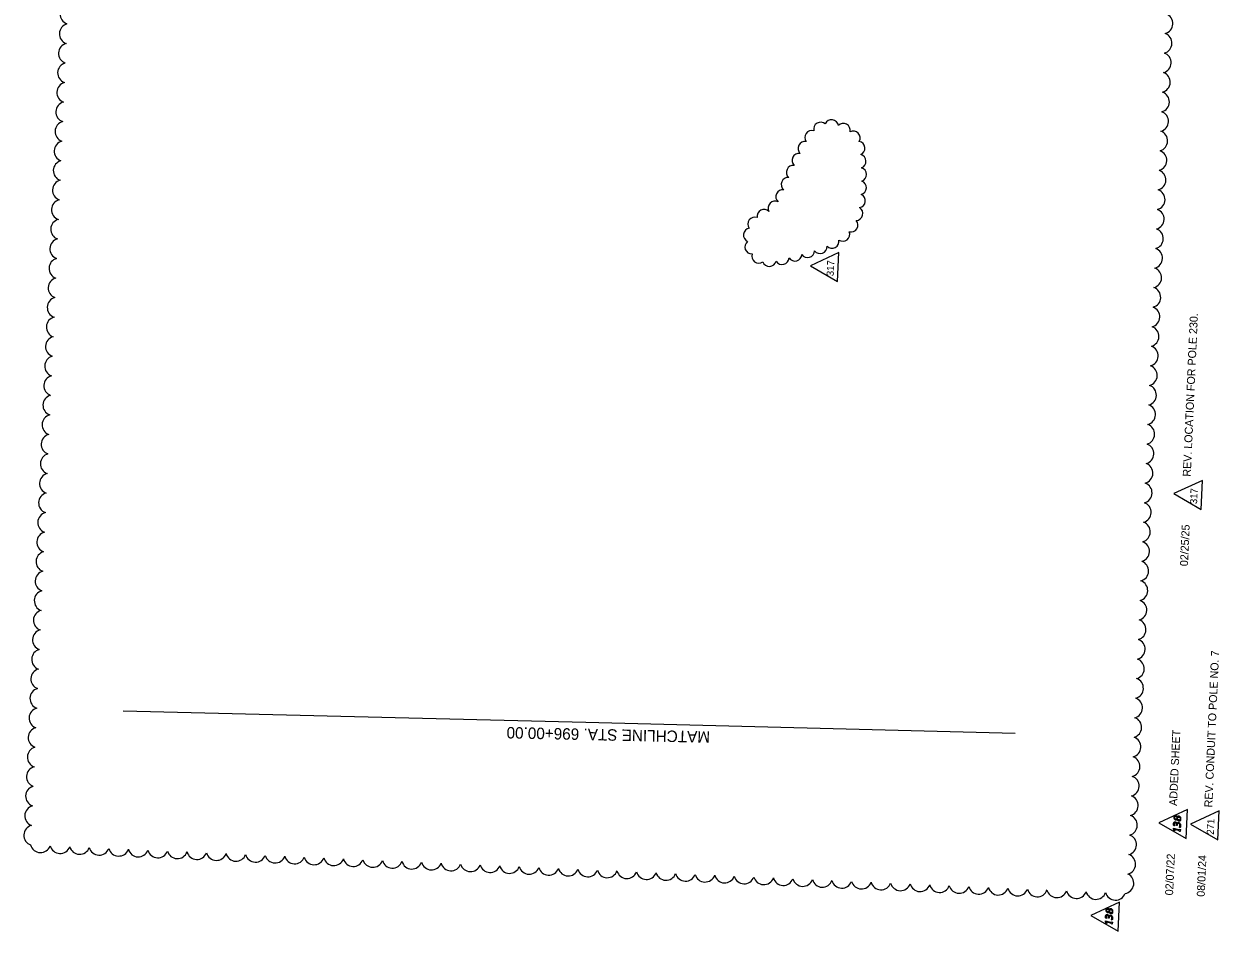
# Model space of a CAD drawing. Extents: x 928596 to 929473, y 645293 to 646588.
# Drawn here: x 928596 to 929432, y 645293 to 645927 of the extents above; entities that cross this region are included whole.
import ezdxf

# ---------------------------------------------------------------- set-up
doc = ezdxf.new("R2010")
doc.units = 0
for name, color, linetype in [('Cloud_dp', 7, 'Continuous'), ('LeaderLine_dp', 7, 'Continuous'), ('PavtAsphalt', 7, 'Continuous'), ('TextBLStation', 7, 'Continuous')]:
    doc.layers.add(name, color=color, linetype=linetype)

msp = doc.modelspace()

# ---------------------------------------------------------------- linework, layer by layer
at = {"layer": 'Cloud_dp'}
for points in [[(929145.88, 645758.1), (929164.93, 645747.11), (929165.83, 645767.37)], [(929400.15, 645598.64), (929419.21, 645587.65), (929420.11, 645607.91)], [(929389.76, 645368.39), (929408.81, 645357.39), (929409.71, 645377.65)], [(929411.88, 645367.41), (929430.93, 645356.41), (929431.83, 645376.67)]]:
    msp.add_lwpolyline(points, close=True, dxfattribs=at)
for points in [[(929400.66, 645366.19), (929400.11, 645366.33)], [(929402.51, 645366.97), (929402.48, 645366.41), (929401.99, 645366.54), (929402.01, 645367.1)], [(929404.16, 645362.38), (929404.18, 645362.81), (929400.45, 645363.78), (929400.8, 645362.74), (929400.18, 645363), (929399.88, 645363.89), (929399.91, 645364.55), (929404.21, 645363.43), (929404.22, 645363.86), (929404.75, 645363.68), (929404.69, 645362.21), (929404.16, 645362.38)], [(929404.59, 645365.02), (929404.02, 645365.18)]]:
    msp.add_lwpolyline(points, dxfattribs=at)
for centre, radius, start, end in [((929160.66, 645855.3), 4.88, 10.34775, 155.34775), ((929146.78, 645847.82), 4.88, 71.57237, 216.57237), ((929153.04, 645853.64), 4.88, 49.19055, 194.19055), ((929168.88, 645852.7), 4.88, 349.57651, 134.57651), ((929175.82, 645847.44), 4.87, 331.1026, 116.1026), ((929142.02, 645840.11), 4.88, 80.0905, 225.0905), ((929179.11, 645840.31), 4.87, 293.42764, 78.42764), ((929137.86, 645831.84), 4.88, 81.54291, 226.54291), ((929179.84, 645831.11), 4.88, 290.65011, 75.65011), ((929133.93, 645823.46), 4.88, 83.18854, 228.18854), ((929180.23, 645821.86), 4.88, 289.24861, 74.24861), ((929130.31, 645814.96), 4.88, 85.63768, 230.63768), ((929180.17, 645812.68), 4.88, 284.95621, 69.95621), ((929126.57, 645806.36), 4.88, 82.32238, 227.32238), ((929121.12, 645798.4), 4.88, 63.88587, 208.88587), ((929179.42, 645803.52), 4.88, 280.64089, 65.64089), ((929106.98, 645787.14), 4.88, 70.43464, 215.43464), ((929113.41, 645792.59), 4.88, 45.1131, 190.1131), ((929177.7, 645794.62), 4.88, 272.5508, 57.5508), ((929103.89, 645779.52), 4.88, 100.46864, 245.46864), ((929174.23, 645786.56), 4.88, 255.8672, 40.8672), ((929160.98, 645775.18), 4.88, 225.07197, 10.07197), ((929168.49, 645780.08), 4.88, 236.10245, 21.10245), ((929104.86, 645771.24), 4.88, 127.87411, 272.87411), ((929143.94, 645768.66), 4.88, 213.21508, 358.21508), ((929152.66, 645771.49), 4.88, 217.76468, 2.76468), ((929109.72, 645764.8), 4.88, 161.1794, 306.1794), ((929117.19, 645762.49), 4.88, 199.49851, 344.49851), ((929126.01, 645763.79), 4.88, 212.2389, 357.2389), ((929134.99, 645766.18), 4.88, 212.67182, 357.67182)]:
    msp.add_arc(centre, radius, start, end, dxfattribs=at)
for points in [[(929400.11, 645366.33), (929400.03, 645366.7), (929400, 645367.04), (929399.96, 645367.37), (929399.97, 645367.66), (929400.01, 645368.4), (929400.35, 645368.74), (929400.62, 645369), (929401.01, 645368.98), (929401.14, 645368.98), (929401.28, 645368.94), (929401.66, 645368.84), (929401.92, 645368.55), (929402.17, 645368.26), (929402.27, 645367.74)], [(929402.45, 645371.06), (929402.31, 645370.61), (929402.01, 645370.46), (929401.82, 645370.35), (929401.57, 645370.36), (929401.45, 645370.37), (929401.32, 645370.4), (929400.76, 645370.54), (929400.45, 645371.03), (929400.14, 645371.52), (929400.18, 645372.22), (929400.21, 645372.94), (929400.55, 645373.26), (929400.82, 645373.5), (929401.2, 645373.48), (929401.33, 645373.47), (929401.48, 645373.44), (929401.87, 645373.33), (929402.14, 645373.04), (929402.41, 645372.74), (929402.5, 645372.23), (929402.64, 645372.72), (929402.98, 645372.9), (929403.19, 645373.02), (929403.47, 645373.01), (929403.61, 645373), (929403.76, 645372.96), (929404.44, 645372.78), (929404.78, 645372.27), (929405.12, 645371.76), (929405.09, 645370.97), (929405.05, 645370.18), (929404.67, 645369.85), (929404.39, 645369.62), (929403.97, 645369.64), (929403.79, 645369.64), (929403.59, 645369.69), (929403.14, 645369.81), (929402.84, 645370.15), (929402.55, 645370.49), (929402.45, 645371.06)], [(929402.01, 645367.1), (929402.03, 645367.58), (929401.85, 645367.9), (929401.66, 645368.22), (929401.29, 645368.31), (929401.19, 645368.34), (929401.1, 645368.34), (929400.87, 645368.35), (929400.72, 645368.2), (929400.5, 645367.98), (929400.48, 645367.49), (929400.47, 645367.23), (929400.51, 645366.9), (929400.56, 645366.58), (929400.66, 645366.19)], [(929401.43, 645371), (929401.54, 645370.97), (929401.64, 645370.96), (929401.87, 645370.95), (929402.02, 645371.08), (929402.24, 645371.26), (929402.26, 645371.68), (929402.28, 645372.11), (929402.07, 645372.41), (929401.86, 645372.72), (929401.48, 645372.81), (929401.37, 645372.84), (929401.28, 645372.85), (929401.05, 645372.86), (929400.9, 645372.73), (929400.67, 645372.54), (929400.66, 645372.12), (929400.64, 645371.69), (929400.84, 645371.39), (929401.05, 645371.1), (929401.43, 645371)], [(929402.27, 645367.74), (929402.41, 645368.23), (929402.73, 645368.41), (929402.95, 645368.53), (929403.22, 645368.52), (929403.36, 645368.52), (929403.51, 645368.48), (929404.21, 645368.3), (929404.56, 645367.72), (929404.92, 645367.14), (929404.88, 645366.25), (929404.87, 645365.94), (929404.79, 645365.64), (929404.72, 645365.33), (929404.59, 645365.02)], [(929404.02, 645365.18), (929404.16, 645365.38), (929404.26, 645365.68), (929404.35, 645365.98), (929404.37, 645366.33), (929404.39, 645366.95), (929404.16, 645367.35), (929403.93, 645367.74), (929403.46, 645367.86), (929403.34, 645367.89), (929403.24, 645367.9), (929402.96, 645367.91), (929402.79, 645367.74), (929402.53, 645367.5), (929402.51, 645366.97)], [(929402.73, 645371.59), (929402.71, 645371.11), (929402.95, 645370.77), (929403.2, 645370.43), (929403.64, 645370.32), (929403.77, 645370.28), (929403.89, 645370.28), (929404.15, 645370.26), (929404.33, 645370.4), (929404.59, 645370.61), (929404.61, 645371.07), (929404.63, 645371.55), (929404.39, 645371.89), (929404.14, 645372.23), (929403.7, 645372.34), (929403.57, 645372.38), (929403.45, 645372.38), (929403.19, 645372.39), (929403.01, 645372.26), (929402.75, 645372.06), (929402.73, 645371.59)]]:
    msp.add_open_spline(points, degree=3, dxfattribs=at)
at = {"layer": 'LeaderLine_dp'}
msp.add_lwpolyline([(929342.17, 645303.59), (929361.23, 645292.6), (929362.13, 645312.86)], close=True, dxfattribs=at)
for points in [[(929356.58, 645297.58), (929356.59, 645298.02), (929352.87, 645298.98), (929353.21, 645297.95), (929352.6, 645298.21), (929352.3, 645299.1), (929352.33, 645299.75), (929356.62, 645298.64), (929356.64, 645299.06), (929357.17, 645298.88), (929357.1, 645297.42), (929356.58, 645297.58)], [(929353.08, 645301.4), (929352.53, 645301.54)], [(929354.93, 645302.17), (929354.9, 645301.61), (929354.4, 645301.75), (929354.43, 645302.3)], [(929357, 645300.23), (929356.43, 645300.38)]]:
    msp.add_lwpolyline(points, dxfattribs=at)
for centre, radius, start, end in [((928628.13, 645933.99), 7.18, 104.96475, 249.96475), ((929392.27, 645927.48), 7.18, 284.96475, 69.96475), ((928627.52, 645920.31), 7.18, 104.96475, 249.96475), ((929391.67, 645913.8), 7.18, 284.96475, 69.96475), ((928626.92, 645906.64), 7.18, 104.96475, 249.96475), ((929391.06, 645900.13), 7.18, 284.96475, 69.96475), ((928626.31, 645892.96), 7.18, 104.96475, 249.96475), ((929390.46, 645886.45), 7.18, 284.96475, 69.96475), ((928625.71, 645879.28), 7.18, 104.96475, 249.96475), ((929389.85, 645872.77), 7.18, 284.96475, 69.96475), ((928625.1, 645865.61), 7.18, 104.96475, 249.96475), ((929389.24, 645859.1), 7.18, 284.96475, 69.96475), ((928624.5, 645851.93), 7.18, 104.96475, 249.96475), ((929388.64, 645845.42), 7.18, 284.96475, 69.96475), ((928623.89, 645838.26), 7.18, 104.96475, 249.96475), ((929388.03, 645831.75), 7.18, 284.96475, 69.96475), ((928623.28, 645824.58), 7.18, 104.96475, 249.96475), ((928622.68, 645810.9), 7.18, 104.96475, 249.96475), ((929387.43, 645818.07), 7.18, 284.96475, 69.96475), ((929386.82, 645804.39), 7.18, 284.96475, 69.96475), ((928622.07, 645797.23), 7.18, 104.96475, 249.96475), ((929386.22, 645790.72), 7.18, 284.96475, 69.96475), ((928621.47, 645783.55), 7.18, 104.96475, 249.96475), ((929385.61, 645777.04), 7.18, 284.96475, 69.96475), ((928620.86, 645769.87), 7.18, 104.96475, 249.96475), ((929385.01, 645763.36), 7.18, 284.96475, 69.96475), ((928620.26, 645756.2), 7.18, 104.96475, 249.96475), ((929384.4, 645749.69), 7.18, 284.96475, 69.96475), ((928619.65, 645742.52), 7.18, 104.96475, 249.96475), ((929383.79, 645736.01), 7.18, 284.96475, 69.96475), ((928619.05, 645728.84), 7.18, 104.96475, 249.96475), ((929383.19, 645722.33), 7.18, 284.96475, 69.96475), ((928618.44, 645715.17), 7.18, 104.96475, 249.96475), ((928617.83, 645701.49), 7.18, 104.96475, 249.96475), ((929382.58, 645708.66), 7.18, 284.96475, 69.96475), ((929381.98, 645694.98), 7.18, 284.96475, 69.96475), ((928617.23, 645687.81), 7.18, 104.96475, 249.96475), ((929381.37, 645681.31), 7.18, 284.96475, 69.96475), ((928616.62, 645674.14), 7.18, 104.96475, 249.96475), ((928616.02, 645660.46), 7.18, 104.96475, 249.96475), ((929380.77, 645667.63), 7.18, 284.96475, 69.96475), ((929380.16, 645653.95), 7.18, 284.96475, 69.96475), ((928615.41, 645646.79), 7.18, 104.96475, 249.96475), ((929379.56, 645640.28), 7.18, 284.96475, 69.96475), ((928614.81, 645633.11), 7.18, 104.96475, 249.96475), ((929378.95, 645626.6), 7.18, 284.96475, 69.96475), ((928614.2, 645619.43), 7.18, 104.96475, 249.96475), ((929378.34, 645612.92), 7.18, 284.96475, 69.96475), ((928613.6, 645605.76), 7.18, 104.96475, 249.96475), ((929377.74, 645599.25), 7.18, 284.96475, 69.96475), ((928612.99, 645592.08), 7.18, 104.96475, 249.96475), ((929377.13, 645585.57), 7.18, 284.96475, 69.96475), ((928612.38, 645578.4), 7.18, 104.96475, 249.96475), ((929376.53, 645571.89), 7.18, 284.96475, 69.96475), ((928611.78, 645564.73), 7.18, 104.96475, 249.96475), ((928611.17, 645551.05), 7.18, 104.96475, 249.96475), ((929375.92, 645558.22), 7.18, 284.96475, 69.96475), ((929375.32, 645544.54), 7.18, 284.96475, 69.96475), ((928610.57, 645537.37), 7.18, 104.96475, 249.96475), ((929374.71, 645530.86), 7.18, 284.96475, 69.96475), ((928609.96, 645523.7), 7.18, 104.96475, 249.96475), ((928609.36, 645510.02), 7.18, 104.96475, 249.96475), ((929374.11, 645517.19), 7.18, 284.96475, 69.96475), ((929373.5, 645503.51), 7.18, 284.96475, 69.96475), ((928608.75, 645496.35), 7.18, 104.96475, 249.96475), ((929372.89, 645489.84), 7.18, 284.96475, 69.96475), ((928608.15, 645482.67), 7.18, 104.96475, 249.96475), ((929372.29, 645476.16), 7.18, 284.96475, 69.96475), ((928607.54, 645468.99), 7.18, 104.96475, 249.96475), ((929371.68, 645462.48), 7.18, 284.96475, 69.96475), ((928606.93, 645455.32), 7.18, 104.96475, 249.96475), ((929371.08, 645448.81), 7.18, 284.96475, 69.96475), ((928606.33, 645441.64), 7.18, 104.96475, 249.96475), ((929370.47, 645435.13), 7.18, 284.96475, 69.96475), ((928605.72, 645427.96), 7.18, 104.96475, 249.96475), ((929369.87, 645421.45), 7.18, 284.96475, 69.96475), ((928605.12, 645414.29), 7.18, 104.96475, 249.96475), ((928604.51, 645400.61), 7.18, 104.96475, 249.96475), ((929369.26, 645407.78), 7.18, 284.96475, 69.96475), ((929368.66, 645394.1), 7.18, 284.96475, 69.96475), ((928603.91, 645386.93), 7.18, 104.96475, 249.96475), ((929368.05, 645380.42), 7.18, 284.96475, 69.96475), ((928603.3, 645373.26), 7.18, 104.96475, 249.96475), ((928602.7, 645359.58), 7.18, 104.96475, 249.96475), ((929367.44, 645366.75), 7.18, 284.96475, 69.96475), ((929366.84, 645353.07), 7.18, 284.96475, 69.96475), ((928607.17, 645354.69), 7.18, 194.96475, 339.96475), ((928620.85, 645354.09), 7.18, 194.96475, 339.96475), ((928634.52, 645353.48), 7.18, 194.96475, 339.96475), ((928648.2, 645352.88), 7.18, 194.96475, 339.96475), ((928661.88, 645352.27), 7.18, 194.96475, 339.96475), ((928675.55, 645351.66), 7.18, 194.96475, 339.96475), ((928689.23, 645351.06), 7.18, 194.96475, 339.96475), ((928702.9, 645350.45), 7.18, 194.96475, 339.96475), ((928716.58, 645349.85), 7.18, 194.96475, 339.96475), ((928730.26, 645349.24), 7.18, 194.96475, 339.96475), ((928743.93, 645348.64), 7.18, 194.96475, 339.96475), ((928757.61, 645348.03), 7.18, 194.96475, 339.96475), ((928771.29, 645347.43), 7.18, 194.96475, 339.96475), ((928784.96, 645346.82), 7.18, 194.96475, 339.96475), ((928798.64, 645346.21), 7.18, 194.96475, 339.96475), ((928812.32, 645345.61), 7.18, 194.96475, 339.96475), ((928825.99, 645345), 7.18, 194.96475, 339.96475), ((928839.67, 645344.4), 7.18, 194.96475, 339.96475), ((928853.35, 645343.79), 7.18, 194.96475, 339.96475), ((928867.02, 645343.19), 7.18, 194.96475, 339.96475), ((928880.7, 645342.58), 7.18, 194.96475, 339.96475), ((929366.23, 645339.4), 7.18, 284.96475, 69.96475), ((928894.37, 645341.98), 7.18, 194.96475, 339.96475), ((928908.05, 645341.37), 7.18, 194.96475, 339.96475), ((928921.73, 645340.76), 7.18, 194.96475, 339.96475), ((928935.4, 645340.16), 7.18, 194.96475, 339.96475), ((928949.08, 645339.55), 7.18, 194.96475, 339.96475), ((928962.76, 645338.95), 7.18, 194.96475, 339.96475), ((928976.43, 645338.34), 7.18, 194.96475, 339.96475), ((928990.11, 645337.74), 7.18, 194.96475, 339.96475), ((929003.79, 645337.13), 7.18, 194.96475, 339.96475), ((929017.46, 645336.53), 7.18, 194.96475, 339.96475), ((929031.14, 645335.92), 7.18, 194.96475, 339.96475), ((929044.81, 645335.31), 7.18, 194.96475, 339.96475), ((929058.49, 645334.71), 7.18, 194.96475, 339.96475), ((929072.17, 645334.1), 7.18, 194.96475, 339.96475), ((929364.97, 645326.01), 7.17, 279.21011, 64.21011), ((929085.84, 645333.5), 7.18, 194.96475, 339.96475), ((929099.52, 645332.89), 7.18, 194.96475, 339.96475), ((929113.2, 645332.29), 7.18, 194.96475, 339.96475), ((929126.87, 645331.68), 7.18, 194.96475, 339.96475), ((929140.55, 645331.08), 7.18, 194.96475, 339.96475), ((929154.23, 645330.47), 7.18, 194.96475, 339.96475), ((929167.9, 645329.86), 7.18, 194.96475, 339.96475), ((929181.58, 645329.26), 7.18, 194.96475, 339.96475), ((929195.26, 645328.65), 7.18, 194.96475, 339.96475), ((929208.93, 645328.05), 7.18, 194.96475, 339.96475), ((929222.61, 645327.44), 7.18, 194.96475, 339.96475), ((929236.28, 645326.84), 7.18, 194.96475, 339.96475), ((929249.96, 645326.23), 7.18, 194.96475, 339.96475), ((929263.64, 645325.63), 7.18, 194.96475, 339.96475), ((929277.31, 645325.02), 7.18, 194.96475, 339.96475), ((929290.99, 645324.41), 7.18, 194.96475, 339.96475), ((929304.67, 645323.81), 7.18, 194.96475, 339.96475), ((929318.34, 645323.2), 7.18, 194.96475, 339.96475), ((929332.02, 645322.6), 7.18, 194.96475, 339.96475), ((929345.7, 645321.99), 7.18, 194.96475, 339.96475), ((929359.37, 645321.39), 7.18, 194.96475, 339.96475)]:
    msp.add_arc(centre, radius, start, end, dxfattribs=at)
for points in [[(929354.86, 645306.26), (929354.73, 645305.82), (929354.43, 645305.66), (929354.23, 645305.56), (929353.99, 645305.57), (929353.87, 645305.57), (929353.73, 645305.6), (929353.17, 645305.75), (929352.87, 645306.24), (929352.56, 645306.72), (929352.59, 645307.43), (929352.62, 645308.14), (929352.97, 645308.46), (929353.23, 645308.7), (929353.61, 645308.69), (929353.74, 645308.68), (929353.89, 645308.65), (929354.29, 645308.54), (929354.56, 645308.24), (929354.82, 645307.94), (929354.92, 645307.43), (929355.06, 645307.92), (929355.39, 645308.1), (929355.61, 645308.22), (929355.88, 645308.21), (929356.02, 645308.21), (929356.17, 645308.17), (929356.85, 645307.99), (929357.2, 645307.48), (929357.54, 645306.97), (929357.5, 645306.18), (929357.47, 645305.38), (929357.08, 645305.06), (929356.81, 645304.82), (929356.39, 645304.84), (929356.21, 645304.85), (929356, 645304.9), (929355.55, 645305.02), (929355.26, 645305.36), (929354.96, 645305.69), (929354.86, 645306.26)], [(929353.84, 645306.2), (929353.96, 645306.17), (929354.06, 645306.17), (929354.28, 645306.16), (929354.44, 645306.28), (929354.65, 645306.46), (929354.67, 645306.89), (929354.69, 645307.31), (929354.49, 645307.62), (929354.28, 645307.92), (929353.9, 645308.02), (929353.79, 645308.05), (929353.69, 645308.05), (929353.46, 645308.06), (929353.31, 645307.93), (929353.09, 645307.75), (929353.07, 645307.33), (929353.05, 645306.9), (929353.26, 645306.6), (929353.46, 645306.3), (929353.84, 645306.2)], [(929355.15, 645306.79), (929355.13, 645306.32), (929355.37, 645305.98), (929355.61, 645305.63), (929356.05, 645305.52), (929356.19, 645305.49), (929356.3, 645305.48), (929356.57, 645305.47), (929356.75, 645305.61), (929357, 645305.81), (929357.02, 645306.28), (929357.05, 645306.75), (929356.8, 645307.09), (929356.56, 645307.44), (929356.12, 645307.55), (929355.98, 645307.58), (929355.87, 645307.59), (929355.6, 645307.6), (929355.43, 645307.46), (929355.17, 645307.26), (929355.15, 645306.79)], [(929352.53, 645301.54), (929352.45, 645301.91), (929352.41, 645302.24), (929352.38, 645302.58), (929352.39, 645302.87), (929352.42, 645303.6), (929352.77, 645303.95), (929353.04, 645304.21), (929353.43, 645304.19), (929353.55, 645304.19), (929353.69, 645304.15), (929354.08, 645304.05), (929354.33, 645303.76), (929354.59, 645303.47), (929354.69, 645302.94)], [(929354.43, 645302.3), (929354.45, 645302.79), (929354.26, 645303.11), (929354.08, 645303.42), (929353.71, 645303.52), (929353.61, 645303.54), (929353.52, 645303.55), (929353.28, 645303.56), (929353.13, 645303.41), (929352.92, 645303.19), (929352.9, 645302.7), (929352.89, 645302.43), (929352.93, 645302.11), (929352.97, 645301.79), (929353.08, 645301.4)], [(929354.69, 645302.94), (929354.82, 645303.44), (929355.15, 645303.62), (929355.36, 645303.74), (929355.64, 645303.73), (929355.78, 645303.72), (929355.93, 645303.68), (929356.62, 645303.5), (929356.98, 645302.93), (929357.33, 645302.35), (929357.3, 645301.45), (929357.28, 645301.15), (929357.21, 645300.85), (929357.14, 645300.54), (929357, 645300.23)], [(929356.43, 645300.38), (929356.58, 645300.58), (929356.67, 645300.89), (929356.77, 645301.19), (929356.78, 645301.54), (929356.81, 645302.16), (929356.58, 645302.55), (929356.34, 645302.95), (929355.88, 645303.07), (929355.76, 645303.1), (929355.65, 645303.1), (929355.38, 645303.12), (929355.2, 645302.95), (929354.95, 645302.71), (929354.93, 645302.17)]]:
    msp.add_open_spline(points, degree=3, dxfattribs=at)
at = {"layer": 'PavtAsphalt'}
msp.add_lwpolyline([(929289.21, 645430.94), (928988.65, 645438.45), (928664.93, 645446.54)], dxfattribs=at)

# ---------------------------------------------------------------- texts
msp.add_text('MATCHLINE STA. 696+00.00', height=8, rotation=178.72942, dxfattribs=at).set_placement((929075.72, 645432.29))
at = {"layer": 'TextBLStation'}
for s, height, p in [('317', 5, (929162.13, 645750.66)), ('REV. LOCATION FOR POLE 230.', 5.6, (929411.98, 645610.41)), ('317', 5, (929416.4, 645591.2)), ('02/25/25', 5.6, (929410.01, 645547.77)), ('REV. CONDUIT TO POLE NO. 7', 5.6, (929427.05, 645379.02)), ('ADDED SHEET', 5.6, (929402.39, 645380.11)), ('271', 5, (929428.13, 645359.97)), ('02/07/22', 5.6, (929399.61, 645317.51)), ('08/01/24', 5.6, (929421.73, 645316.53))]:
    msp.add_text(s, height=height, rotation=87.46475, dxfattribs=at).set_placement(p)

doc.saveas('drawing.dxf')
